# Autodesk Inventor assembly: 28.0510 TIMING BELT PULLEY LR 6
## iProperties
Created: 2007-06
Part Number: 28.0510 TIMING BELT PULLEY LR 6
Document SubType Name: Assembly
Designer: Andy Moles
Author: Andy Moles
